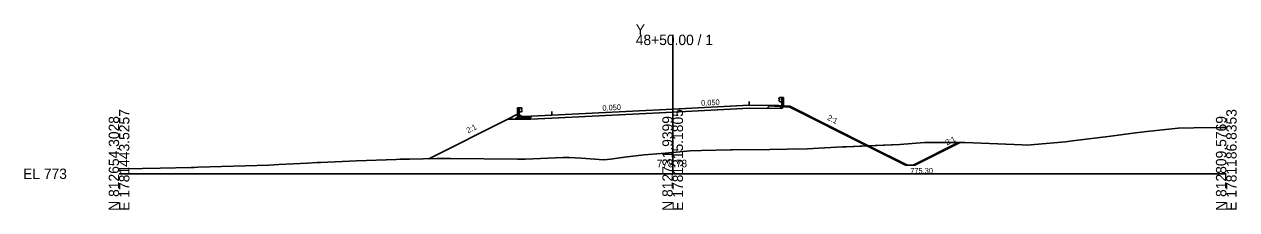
# Model space of a CAD drawing. Extents: x -12583 to 5303, y -44 to 25667.
# Drawn here: x 2974.3 to 3302.8, y 8990.3 to 9040.4 of the extents above; entities that cross this region are included whole.
import ezdxf

# ---------------------------------------------------------------- set-up
doc = ezdxf.new("R2010")
doc.units = 0
for name, color, linetype in [('Exist Cross Section Cell', 7, 'Continuous'), ('Exist XS Center Line Elevation Label', 7, 'Continuous'), ('Exist XS Ground Line', 7, 'Continuous'), ('Prop XS Ditch Standard Text', 7, 'Continuous'), ('Prop XS Dump Level', 7, 'Continuous'), ('Prop XS Earthwork Shape', 7, 'Continuous'), ('Prop XS EOT Tick Mark', 7, 'Continuous'), ('Prop XS Finish Grade', 7, 'Continuous'), ('Prop XS Finish Grade CurbGutter', 7, 'Continuous'), ('Prop XS Finish Grade Earthwork', 7, 'Continuous'), ('Prop XS Finish Grade Paved Shoulder', 7, 'Continuous'), ('Prop XS Finish Grade Pavement', 7, 'Continuous'), ('Prop XS Guardrail', 7, 'Continuous'), ('Prop XS Pvmt Edge Slope', 7, 'Continuous'), ('Prop XS SE Text', 7, 'Continuous'), ('Prop XS Side Slope Text', 7, 'Continuous'), ('Prop XS Subgrade CurbGutter', 7, 'Continuous'), ('Prop XS Subgrade Earthwork', 7, 'Continuous')]:
    doc.layers.add(name, color=color, linetype=linetype)

msp = doc.modelspace()

# ---------------------------------------------------------------- linework, layer by layer
at = {"layer": 'Exist Cross Section Cell'}
for p, q in [((3150, 9000), (3150, 9037.58)), ((3000, 9000), (3150, 9000)), ((3150, 9000), (3300, 9000))]:
    msp.add_line(p, q, dxfattribs=at)
at = {"layer": 'Exist XS Ground Line'}
for p, q in [((3278.44, 9011.41), (3286.96, 9012.32)), ((3286.96, 9012.32), (3291.22, 9012.43)), ((3291.22, 9012.43), (3298.62, 9012.53)), ((3298.62, 9012.53), (3300, 9012.52)), ((3211.57, 9007.95), (3218.24, 9008.42)), ((3218.24, 9008.42), (3228.04, 9008.43)), ((3228.04, 9008.43), (3228.86, 9008.43)), ((3228.86, 9008.43), (3229.17, 9008.42)), ((3229.17, 9008.42), (3238.14, 9008.12)), ((3245.97, 9007.75), (3256.45, 9008.67)), ((3256.45, 9008.67), (3258.34, 9008.88)), ((3258.34, 9008.88), (3268.73, 9010.18)), ((3268.73, 9010.18), (3275.4, 9011.05)), ((3275.4, 9011.05), (3278.44, 9011.41)), ((3136.96, 9004.49), (3142.3, 9005.14)), ((3142.3, 9005.14), (3146.92, 9005.52)), ((3146.92, 9005.52), (3150, 9005.78)), ((3150, 9005.78), (3154.73, 9006.18)), ((3154.73, 9006.18), (3157.82, 9006.3)), ((3157.82, 9006.3), (3165.68, 9006.47)), ((3165.68, 9006.47), (3166.08, 9006.48)), ((3166.08, 9006.48), (3176.31, 9006.6)), ((3176.31, 9006.6), (3181.03, 9006.65)), ((3181.03, 9006.65), (3186.43, 9006.79)), ((3186.43, 9006.79), (3196.05, 9007.29)), ((3196.05, 9007.29), (3196.76, 9007.32)), ((3196.76, 9007.32), (3197.14, 9007.33)), ((3197.14, 9007.33), (3211.57, 9007.95)), ((3238.14, 9008.12), (3244.71, 9007.81)), ((3244.71, 9007.81), (3245.97, 9007.75)), ((3021.31, 9001.75), (3040.55, 9002.33)), ((3040.55, 9002.33), (3043.33, 9002.52)), ((3043.33, 9002.52), (3051.03, 9002.91)), ((3051.03, 9002.91), (3053.65, 9003.02)), ((3053.65, 9003.02), (3054.71, 9003.09)), ((3054.71, 9003.09), (3064.3, 9003.48)), ((3064.3, 9003.48), (3075.06, 9003.9)), ((3075.06, 9003.9), (3076.19, 9003.93)), ((3076.19, 9003.93), (3078.68, 9003.97)), ((3078.68, 9003.97), (3086.1, 9004.1)), ((3086.1, 9004.1), (3089.8, 9004.1)), ((3089.8, 9004.1), (3107.98, 9003.93)), ((3107.98, 9003.93), (3110.05, 9003.93)), ((3110.05, 9003.93), (3120.36, 9004.43)), ((3120.36, 9004.43), (3121.99, 9004.44)), ((3121.99, 9004.44), (3125.2, 9004.21)), ((3125.2, 9004.21), (3131.36, 9003.75)), ((3131.36, 9003.75), (3133.11, 9003.98)), ((3133.11, 9003.98), (3136.96, 9004.49)), ((3000, 9001.3), (3000.39, 9001.31)), ((3000.39, 9001.31), (3006.35, 9001.45)), ((3006.35, 9001.45), (3011.1, 9001.56)), ((3011.1, 9001.56), (3019.52, 9001.71)), ((3019.52, 9001.71), (3020.35, 9001.73)), ((3020.35, 9001.73), (3021.31, 9001.75))]:
    msp.add_line(p, q, dxfattribs=at)
at = {"layer": 'Prop XS Dump Level'}
for p, q in [((3150, 9017.48), (3170.75, 9018.52)), ((3117.25, 9015.84), (3150, 9017.48))]:
    msp.add_line(p, q, dxfattribs=at)
at = {"layer": 'Prop XS Earthwork Shape'}
for points in [[(3176.24, 9018.37), (3181.75, 9017.99), (3202.59, 9007.57), (3197.14, 9007.33), (3196.76, 9007.32), (3196.05, 9007.29), (3186.43, 9006.79), (3181.03, 9006.65), (3176.31, 9006.6), (3166.08, 9006.48), (3165.68, 9006.47), (3157.82, 9006.3), (3154.73, 9006.18), (3150, 9005.78), (3146.92, 9005.52), (3142.3, 9005.14), (3136.96, 9004.49), (3133.11, 9003.98), (3131.36, 9003.75), (3125.2, 9004.21), (3121.99, 9004.44), (3120.36, 9004.43), (3110.05, 9003.93), (3107.98, 9003.93), (3089.8, 9004.1), (3086.1, 9004.1), (3083.91, 9004.06), (3105.32, 9014.76), (3107.19, 9014.76), (3111.58, 9014.76), (3117.29, 9015.05), (3150.04, 9016.69), (3170.77, 9017.72), (3175.55, 9017.68)], [(3202.59, 9007.57), (3211.57, 9007.95), (3218.24, 9008.42), (3227.39, 9008.43), (3215.13, 9002.3), (3213.13, 9002.3)]]:
    msp.add_lwpolyline(points, close=True, dxfattribs=at)
at = {"layer": 'Prop XS EOT Tick Mark'}
for p, q in [((3170.75, 9018.52), (3170.75, 9019.52)), ((3117.25, 9015.84), (3117.25, 9016.84))]:
    msp.add_line(p, q, dxfattribs=at)
at = {"layer": 'Prop XS Finish Grade'}
for p, q in [((3178.75, 9018.44), (3180.24, 9018.33)), ((3105.32, 9014.76), (3107.98, 9016.09)), ((3108.56, 9015.8), (3107.98, 9016.09))]:
    msp.add_line(p, q, dxfattribs=at)
at = {"layer": 'Prop XS Finish Grade CurbGutter'}
for p, q in [((3109.25, 9015.46), (3108.56, 9015.8)), ((3111.58, 9015.56), (3109.25, 9015.46))]:
    msp.add_line(p, q, dxfattribs=at)
at = {"layer": 'Prop XS Finish Grade Earthwork'}
for p, q in [((3180.24, 9018.33), (3181.75, 9018.23)), ((3181.75, 9018.23), (3203.03, 9007.59)), ((3105.32, 9014.76), (3083.91, 9004.06)), ((3215.61, 9002.3), (3227.88, 9008.43)), ((3203.03, 9007.59), (3213.61, 9002.3)), ((3213.61, 9002.3), (3215.61, 9002.3))]:
    msp.add_line(p, q, dxfattribs=at)
at = {"layer": 'Prop XS Finish Grade Paved Shoulder'}
for p, q in [((3170.75, 9018.52), (3178.75, 9018.44)), ((3117.25, 9015.84), (3111.58, 9015.56))]:
    msp.add_line(p, q, dxfattribs=at)
at = {"layer": 'Prop XS Finish Grade Pavement'}
for p, q in [((3150, 9017.48), (3170.75, 9018.52)), ((3117.25, 9015.84), (3150, 9017.48))]:
    msp.add_line(p, q, dxfattribs=at)
at = {"layer": 'Prop XS Guardrail'}
for p, q in [((3178.78, 9020.4), (3178.75, 9020.34)), ((3178.75, 9020.34), (3178.78, 9020.28)), ((3178.78, 9019.79), (3178.75, 9019.73)), ((3178.75, 9019.73), (3178.78, 9019.67)), ((3179.07, 9020.6), (3178.78, 9020.4)), ((3178.78, 9020.28), (3179.07, 9020.08)), ((3179.07, 9019.99), (3178.78, 9019.79)), ((3178.78, 9019.67), (3179.07, 9019.47)), ((3179.57, 9020.6), (3179.07, 9020.6)), ((3179.07, 9020.08), (3179.07, 9019.99)), ((3179.07, 9019.47), (3179.57, 9019.47)), ((3180.07, 9020.6), (3179.57, 9020.6)), ((3179.57, 9020.6), (3179.57, 9018.1)), ((3180.07, 9018.1), (3180.07, 9020.6)), ((3107.93, 9017.86), (3108.43, 9017.86)), ((3107.93, 9015.36), (3107.93, 9017.86)), ((3108.43, 9017.86), (3108.93, 9017.86)), ((3108.43, 9017.86), (3108.43, 9015.36)), ((3108.93, 9016.72), (3108.43, 9016.72)), ((3108.93, 9017.86), (3109.22, 9017.66)), ((3109.22, 9017.54), (3108.93, 9017.34)), ((3108.93, 9017.34), (3108.93, 9017.24)), ((3108.93, 9017.24), (3109.22, 9017.04)), ((3109.22, 9016.92), (3108.93, 9016.72)), ((3109.22, 9017.66), (3109.25, 9017.6)), ((3109.25, 9017.6), (3109.22, 9017.54)), ((3109.22, 9017.04), (3109.25, 9016.98)), ((3109.25, 9016.98), (3109.22, 9016.92))]:
    msp.add_line(p, q, dxfattribs=at)
at = {"layer": 'Prop XS Pvmt Edge Slope'}
for p, q in [((3178.75, 9018.44), (3179.55, 9017.64)), ((3107.56, 9015.14), (3107.19, 9014.76)), ((3108.56, 9015.14), (3107.56, 9015.14))]:
    msp.add_line(p, q, dxfattribs=at)
at = {"layer": 'Prop XS Subgrade CurbGutter'}
for p, q in [((3108.56, 9015.14), (3108.56, 9015.8)), ((3111.58, 9015.14), (3108.56, 9015.14)), ((3111.58, 9015.56), (3111.58, 9015.14))]:
    msp.add_line(p, q, dxfattribs=at)
at = {"layer": 'Prop XS Subgrade Earthwork'}
for p, q in [((3179.55, 9017.64), (3180.24, 9018.33)), ((3117.29, 9015.05), (3111.58, 9014.76)), ((3117.29, 9015.05), (3150.04, 9016.69)), ((3150.04, 9016.69), (3170.77, 9017.72)), ((3170.77, 9017.72), (3179.55, 9017.64)), ((3107.19, 9014.76), (3105.32, 9014.76)), ((3111.58, 9014.76), (3107.19, 9014.76))]:
    msp.add_line(p, q, dxfattribs=at)

# ---------------------------------------------------------------- texts
at = {"layer": 'Exist Cross Section Cell'}
for s, p in [('Y', (3140, 9037.58)), ('48+50.00 / 1', (3140, 9034.78)), ('EL 773', (2974, 8998.6))]:
    msp.add_text(s, height=2.8, dxfattribs=at).set_placement(p)
for s, p in [('N 812654.3028', (3000, 8990)), ('E 1781443.5257', (3002.8, 8990)), ('N 812731.9399', (3150, 8990)), ('E 1781315.1805', (3152.8, 8990)), ('N 812809.5769', (3300, 8990)), ('E 1781186.8353', (3302.8, 8990))]:
    msp.add_text(s, height=2.8, rotation=90, dxfattribs=at).set_placement(p)
at = {"layer": 'Exist XS Center Line Elevation Label'}
msp.add_text('778.78', height=2, dxfattribs=at).set_placement((3145.73, 9001.78))
at = {"layer": 'Prop XS Ditch Standard Text'}
msp.add_text('775.30', height=1.5, dxfattribs=at).set_placement((3214.39, 9000.09))
at = {"layer": 'Prop XS Dump Level'}
msp.add_text('Case2', height=0.04, dxfattribs=at).set_placement((3178.75, 9018.16))
at = {"layer": 'Prop XS SE Text'}
for p in [(3131, 9017.03), (3157.75, 9018.37)]:
    msp.add_text('0.050', height=1.5, rotation=2.8624, dxfattribs=at).set_placement(p)
at = {"layer": 'Prop XS Side Slope Text'}
for rotation, p in [(333.4349, (3191.75, 9014.66)), (26.5651, (3094.56, 9010.91)), (26.5651, (3224.34, 9007.66))]:
    msp.add_text('2:1', height=1.5, rotation=rotation, dxfattribs=at).set_placement(p)

doc.saveas('drawing.dxf')
